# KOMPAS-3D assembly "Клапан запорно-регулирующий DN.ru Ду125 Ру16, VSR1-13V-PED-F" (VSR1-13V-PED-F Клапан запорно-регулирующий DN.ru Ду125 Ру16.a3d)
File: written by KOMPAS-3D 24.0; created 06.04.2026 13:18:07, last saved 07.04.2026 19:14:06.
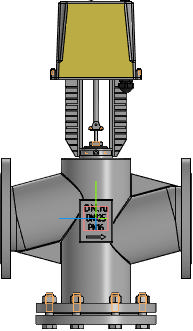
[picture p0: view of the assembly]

Document properties: Автор: R2D2; Полное имя файла: E:\Работа\Зайцев\Солянка\VSR1-13V-PED-F Клапан запорно-регулирующий DN.ru\DN125\исходные материалы\VSR1-13V-PED-F Клапан запорно-регулирующий DN.ru Ду125 Ру16.a3d

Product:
- Component [detail]: Фланец  | qty 2  | pos. 1  | Масса: 5.514788; Автор: R2D2; source file: Фланец.m3d
- Component [detail]: Фланец  | qty 1  | pos. 2  | Масса: 5.514788; Автор: R2D2; source file: Фланец.m3d
- Component [detail]: Корпус  | qty 1  | pos. 3  | Масса: 6.9; Автор: R2D2; source file: Корпус.m3d
- Component [detail]: Электропривод  | qty 1  | pos. 6  | Масса: 0.101125; Автор: R2D2; source file: Электропривод.m3d
- Component [standard]: Болт с шестигранной головкой ГОСТ Р ИСО 4014 - М16 x 65  | qty 8  | Материал: Не определено (density 1000 kg/m3); Масса: 0.1404; Раздел спецификации: Стандартные изделия; Рассекать на разрезах: no; additional columns: ГОСТ Р ИСО 4014-2013
- Component [standard]: Гайка М16-6H ГОСТ 5915-70  | qty 8  | Масса: 0.03761; Раздел спецификации: Стандартные изделия; Рассекать на разрезах: no; additional columns: М1,6-6H
- Part/product: Клапан запорно-регулирующий DN.ru Ду125 Ру16  | designation VSR1-13V-PED-F
    Масса: 40.6
    Раздел спецификации: Прочие изделия
    Примечание: D090-02895

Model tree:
1. Эскиз:1
2. Ось конической поверхности:19
3. Смещенная плоскость:19
4. ЛСК:19  (with: Плоскость XY, Плоскость ZX, Плоскость ZY, Ось X, Ось Y, Ось Z)
     Ось X. Y = -1; Ось Y. X = 1; Ось Z. Z = 1; Точка начала. Х = -40.1818; Точка начала. Y = -220; Точка начала. Z = -97.0074
5. Болтовое соединение
6. Массив по концентрической сетке:3  (with: Грань.Элемент выдавливания:1, Грань.Элемент вращения:1, Грань.Элемент выдавливания:8)  (8 pattern instances)
     Шаг 2 = 360; Ориентация = 2; Расстояние = -44

Expressions: VSR1-13V-PED-F; -L/2
Referenced files in E:\Работа\Зайцев\Солянка\VSR1-13V-PED-F Клапан запорно-регулирующий DN.ru\DN125\исходные материалы\: Фланец.m3d, Корпус.m3d, Электропривод.m3d
Referenced files in C:\Program Files\ASCON\KOMPAS-3D v24\Libs\PolynomLib\DATA\vault\Methods\Kompas\3D\: PLib_Bolt_1_ISO_1100.m3d, PLib_Nut_OST92_900.m3d
Referenced files in E:\Работа\Зайцев\Солянка\VSR1-13V-PED-F Клапан запорно-регулирующий DN.ru\DN20\исходные материалы\: Фланец.m3d
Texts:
  Болт с шестигранной головкой
  Крепежное изделие ГОСТ
  Программные изделия  и базы данных
  Edge1
  Edge2
  TKR3D
  Справочник стандартных изделий
  Фланец (1)
  Фланец (2)
  Фланец (3)
  Болт с шестигранной головкой ГОСТ Р ИСО 4014 - М16 x 65 (1)
  hole1
  hole2
  Гайка М16-6H ГОСТ 5915-70 (1)
  bcut1
  hcut1
  cut1
  Плоскость XY.Начало координат
  Ось Z.Начало координат
  Плоскость ZY.Начало координат
  Плоскость ZX.Начало координат
  Ось Y.Начало координат
  Plane. Начало координат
